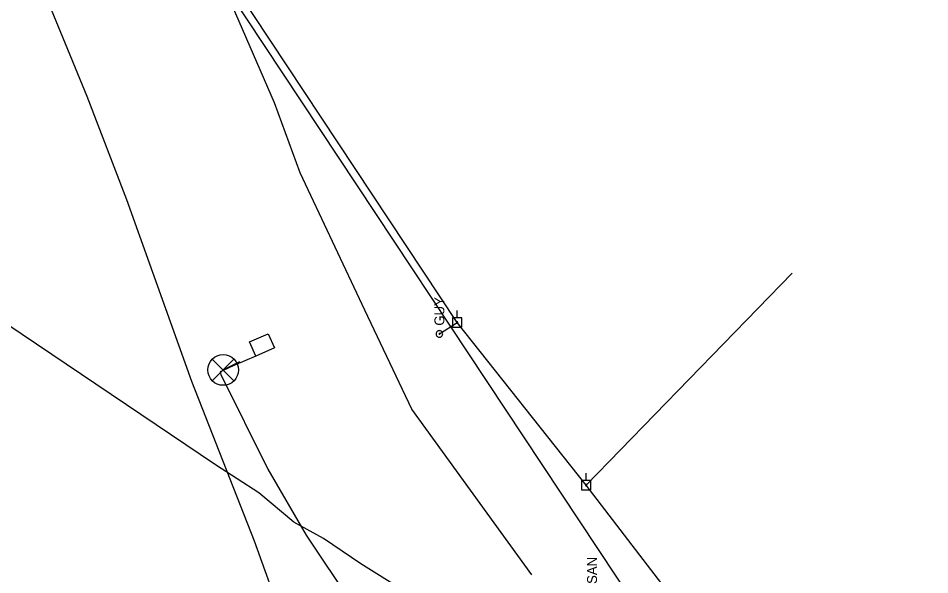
# Model space of a CAD drawing. Extents: x 596028 to 606371, y 330010 to 403088.
# Drawn here: x 602492.8 to 602848.9, y 353695.5 to 353912.9 of the extents above; entities that cross this region are included whole.
import ezdxf

# ---------------------------------------------------------------- set-up
doc = ezdxf.new("R2010")
doc.units = 0
for name, color, linetype in [('E_SIG', 7, 'Continuous'), ('E_UTL_EGuyWire', 7, 'Continuous'), ('E_UTL_EPowerPole', 7, 'Continuous'), ('E_UTL_G_UG', 7, 'Continuous'), ('E_UTL_Loop_UG', 7, 'Continuous'), ('E_UTL_Overhead', 7, 'Continuous'), ('E_UTL_SAN_MH', 7, 'Continuous'), ('E_UTL_T_UG', 7, 'Continuous'), ('E_UTL_W_UG', 7, 'Continuous')]:
    doc.layers.add(name, color=color, linetype=linetype)

msp = doc.modelspace()

# ---------------------------------------------------------------- linework, layer by layer
at = {"layer": 'E_SIG'}
for points in [[(602576.99, 353779.79), (602568.61, 353771.33)], [(602568.61, 353779.71), (602577.07, 353771.25)], [(602572.87, 353775.57), (602579.41, 353778.8)], [(602571.72, 353774.84), (602571.97, 353773.77), (602590.27, 353736.74), (602605.34, 353711.08), (602623.14, 353684.38), (602630.1, 353677.26), (602640.77, 353664.51), (602660.07, 353643.26), (602682.9, 353621.55), (602701.56, 353603.51), (602717.69, 353590.29)]]:
    msp.add_lwpolyline(points, dxfattribs=at)
msp.add_circle((602572.87, 353775.55), 6, dxfattribs=at)
at = {"layer": 'E_UTL_EGuyWire'}
msp.add_line((602657.34, 353789.63), (602664.33, 353794.06), dxfattribs=at)
for points in [[(602657.34, 353790.92), (602657.1, 353790.89), (602656.87, 353790.82), (602656.65, 353790.71), (602656.46, 353790.56), (602656.3, 353790.38), (602656.18, 353790.17), (602656.1, 353789.93), (602656.06, 353789.69), (602656.07, 353789.45), (602656.13, 353789.21), (602656.23, 353788.99), (602656.37, 353788.79), (602656.55, 353788.62), (602656.76, 353788.49), (602656.98, 353788.4), (602657.22, 353788.35), (602657.47, 353788.35), (602657.71, 353788.4), (602657.93, 353788.49), (602658.14, 353788.62), (602658.31, 353788.79), (602658.46, 353788.99), (602658.56, 353789.21), (602658.61, 353789.45), (602658.63, 353789.69), (602658.59, 353789.93), (602658.51, 353790.17), (602658.39, 353790.38), (602658.23, 353790.56), (602658.04, 353790.71), (602657.82, 353790.82), (602657.59, 353790.89), (602657.34, 353790.92)], [(602657.34, 353789.79), (602657.31, 353789.79), (602657.29, 353789.78), (602657.26, 353789.77), (602657.23, 353789.75), (602657.21, 353789.73), (602657.2, 353789.7), (602657.19, 353789.67), (602657.18, 353789.64), (602657.19, 353789.61), (602657.19, 353789.58), (602657.21, 353789.55), (602657.22, 353789.53), (602657.25, 353789.51), (602657.27, 353789.49), (602657.3, 353789.48), (602657.33, 353789.47), (602657.36, 353789.47), (602657.39, 353789.48), (602657.42, 353789.49), (602657.44, 353789.51), (602657.47, 353789.53), (602657.48, 353789.55), (602657.5, 353789.58), (602657.5, 353789.61), (602657.5, 353789.64), (602657.5, 353789.67), (602657.49, 353789.7), (602657.48, 353789.73), (602657.46, 353789.75), (602657.43, 353789.77), (602657.4, 353789.78), (602657.38, 353789.79), (602657.34, 353789.79)]]:
    msp.add_lwpolyline(points, dxfattribs=at)
at = {"layer": 'E_UTL_EPowerPole'}
for points in [[(602664.29, 353795.9), (602664.29, 353798.81)], [(602666.14, 353795.9), (602662.45, 353795.9)], [(602662.45, 353795.9), (602662.45, 353792.21)], [(602664.57, 353794.06), (602664.56, 353794.1), (602664.55, 353794.14), (602664.53, 353794.18), (602664.5, 353794.22), (602664.47, 353794.25), (602664.43, 353794.27), (602664.38, 353794.29), (602664.34, 353794.29), (602664.29, 353794.29), (602664.25, 353794.28), (602664.21, 353794.26), (602664.17, 353794.24), (602664.14, 353794.2), (602664.11, 353794.16), (602664.1, 353794.12), (602664.09, 353794.08), (602664.09, 353794.03), (602664.1, 353793.99), (602664.11, 353793.95), (602664.14, 353793.91), (602664.17, 353793.88), (602664.21, 353793.85), (602664.25, 353793.83), (602664.29, 353793.82), (602664.34, 353793.82), (602664.38, 353793.82), (602664.43, 353793.84), (602664.47, 353793.86), (602664.5, 353793.89), (602664.53, 353793.93), (602664.55, 353793.97), (602664.56, 353794.01), (602664.57, 353794.06)], [(602666.14, 353792.21), (602666.14, 353795.9)], [(602662.45, 353792.21), (602666.14, 353792.21)], [(602714.67, 353732.36), (602714.67, 353735.27)], [(602716.51, 353732.36), (602712.82, 353732.36)], [(602712.82, 353732.36), (602712.82, 353728.67)], [(602714.94, 353730.52), (602714.93, 353730.56), (602714.92, 353730.6), (602714.9, 353730.64), (602714.87, 353730.68), (602714.84, 353730.71), (602714.8, 353730.73), (602714.75, 353730.75), (602714.71, 353730.75), (602714.66, 353730.75), (602714.62, 353730.74), (602714.58, 353730.72), (602714.54, 353730.7), (602714.51, 353730.66), (602714.49, 353730.62), (602714.47, 353730.58), (602714.46, 353730.54), (602714.46, 353730.49), (602714.47, 353730.45), (602714.49, 353730.41), (602714.51, 353730.37), (602714.54, 353730.34), (602714.58, 353730.31), (602714.62, 353730.29), (602714.66, 353730.28), (602714.71, 353730.28), (602714.75, 353730.28), (602714.8, 353730.3), (602714.84, 353730.32), (602714.87, 353730.35), (602714.9, 353730.39), (602714.92, 353730.43), (602714.93, 353730.47), (602714.94, 353730.52)], [(602716.51, 353728.67), (602716.51, 353732.36)], [(602712.82, 353728.67), (602716.51, 353728.67)]]:
    msp.add_lwpolyline(points, dxfattribs=at)
at = {"layer": 'E_UTL_G_UG'}
for points in [[(602733.76, 353683.78), (602567.33, 353935.25)], [(602663.79, 353676.69), (602626.6, 353699.86), (602612.06, 353709.74), (602600.45, 353716.14), (602586.79, 353727.58), (602569.93, 353738.55), (602325.24, 353903.29), (602317.34, 353906.33), (602299.51, 353921.31)]]:
    msp.add_lwpolyline(points, dxfattribs=at)
at = {"layer": 'E_UTL_Loop_UG'}
for p, q in [((602583.15, 353786.48), (602590.47, 353789.71)), ((602585.58, 353780.99), (602583.15, 353786.48)), ((602590.47, 353789.71), (602592.89, 353784.22)), ((602592.89, 353784.22), (602585.58, 353780.99)), ((602585.58, 353780.99), (602577.01, 353777.29))]:
    msp.add_line(p, q, dxfattribs=at)
msp.add_lwpolyline([(602577.01, 353777.29), (602572.66, 353775.15), (602571.72, 353774.84)], dxfattribs=at)
at = {"layer": 'E_UTL_Overhead'}
for points in [[(602931.16, 353554.23), (602765.19, 353664.71), (602714.7, 353730.52), (602664.33, 353794.06), (602564.68, 353944.62)], [(602714.7, 353730.52), (602795.19, 353813.34)]]:
    msp.add_lwpolyline(points, dxfattribs=at)
at = {"layer": 'E_UTL_T_UG'}
msp.add_lwpolyline([(602693.46, 353695.55), (602646.51, 353760.23), (602628.18, 353798.86), (602602.98, 353852.57), (602592.94, 353879.83), (602562.66, 353949.5), (602514.41, 354079.79)], dxfattribs=at)
at = {"layer": 'E_UTL_W_UG'}
msp.add_lwpolyline([(602643.19, 353555.03), (602621.27, 353609.47), (602607.78, 353645.67), (602585.05, 353708.63), (602560.68, 353771.1), (602535.24, 353841.98), (602519.71, 353882.33), (602499.1, 353932.56)], dxfattribs=at)

# ---------------------------------------------------------------- texts
at = {"layer": 'E_UTL_EGuyWire'}
msp.add_text('GUY', height=3.85, rotation=90, dxfattribs=at).set_placement((602659.27, 353792.84))
at = {"layer": 'E_UTL_SAN_MH'}
msp.add_text('SAN', height=3.849, rotation=90, dxfattribs=at).set_placement((602718.9, 353691.96))

doc.saveas('drawing.dxf')
